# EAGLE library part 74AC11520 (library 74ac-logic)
8-bit IDENTITY COMPARATOR
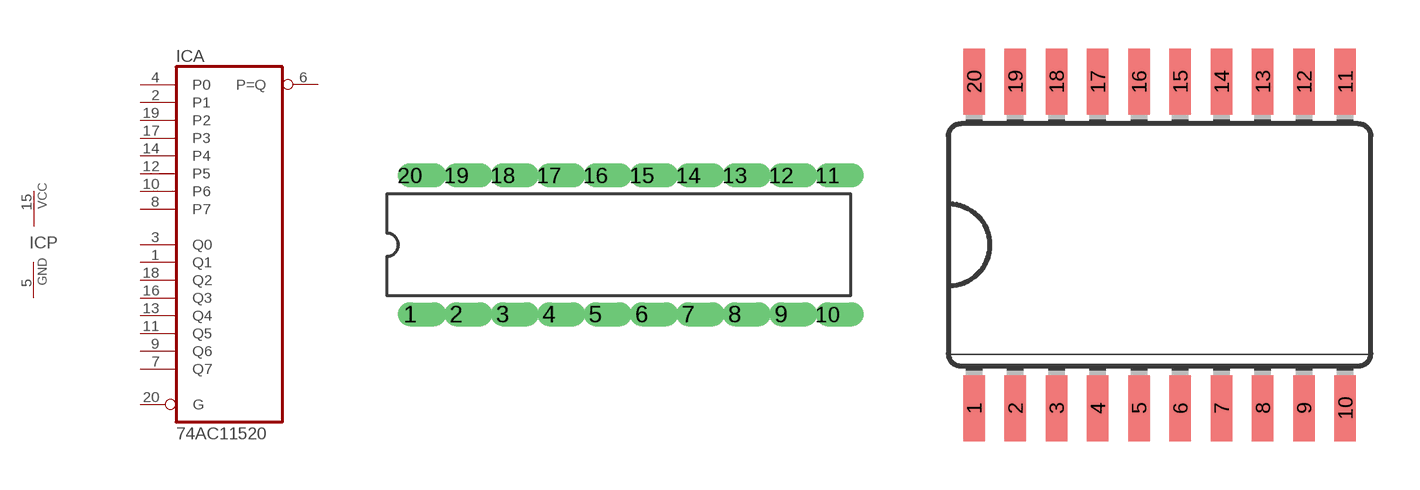
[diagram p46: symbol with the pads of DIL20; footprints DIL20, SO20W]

Designator prefix IC; gates A=7411520 P=PWRN

## 74AC11520  [DIL20]
1  A:Q1  in
2  A:P1  in
3  A:Q0  in
4  A:P0  in
5  P:GND  pwr
6  A:P=Q  out
7  A:Q7  in
8  A:P7  in
9  A:Q6  in
10  A:P6  in
11  A:Q5  in
12  A:P5  in
13  A:Q4  in
14  A:P4  in
15  P:VCC  pwr
16  A:Q3  in
17  A:P3  in
18  A:Q2  in
19  A:P2  in
20  A:G  in

## 74AC11520D  [SO20W]
Pads as for DIL20

## Footprint DIL20 (pad centres in mm)
Dual In Line
drill 0.813 offset: 1 -11.43,-3.81; 2 -8.89,-3.81; 3 -6.35,-3.81; 4 -3.81,-3.81; 5 -1.27,-3.81; 6 1.27,-3.81; 7 3.81,-3.81; 8 6.35,-3.81; 9 8.89,-3.81; 10 11.43,-3.81; 11 11.43,3.81; 12 8.89,3.81; 13 6.35,3.81; 14 3.81,3.81; 15 1.27,3.81; 16 -1.27,3.81; 17 -3.81,3.81; 18 -6.35,3.81; 19 -8.89,3.81; 20 -11.43,3.81

## Footprint SO20W (pad centres in mm)
Wide Small Outline package 300 mil
smd 0.66 x 2.032: 1 -5.715,-5.029; 2 -4.445,-5.029; 3 -3.175,-5.029; 4 -1.905,-5.029; 5 -0.635,-5.029; 6 0.635,-5.029; 7 1.905,-5.029; 8 3.175,-5.029; 9 4.445,-5.029; 10 5.715,-5.029; 11 5.715,5.029; 12 4.445,5.029; 13 3.175,5.029; 14 1.905,5.029; 15 0.635,5.029; 16 -0.635,5.029; 17 -1.905,5.029; 18 -3.175,5.029; 19 -4.445,5.029; 20 -5.715,5.029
